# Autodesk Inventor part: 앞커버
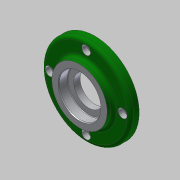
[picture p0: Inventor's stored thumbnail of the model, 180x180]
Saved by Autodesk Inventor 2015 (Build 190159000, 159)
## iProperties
Created: 2019-01
Part Number: 앞커버
Material: 알루미늄 6061
Document SubType Name: Modeling
Designer: mduedu
Density: 1 g/cm^3
Appearance: 알루미늄 - 평지
Author: mduedu
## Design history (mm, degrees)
sketch "스케치1"
  geometry: L1 (0, 0)-(6, 0); L2 (6, 0)-(6, 25); L3 (6, 25)-(0, 25); L4 (0, 25)-(0, 0); L5 (6, 0)-(14, 0); L6 (14, 0)-(14, 40); L7 (14, 40)-(6, 40); L8 (6, 40)-(6, 0); L9 (14, 0)-(19, 0); L10 (19, 0)-(19, 26); L11 (19, 26)-(14, 26); L12 (14, 26)-(14, 0)
  constraints: 24 end point, 6 parallel, 3 horizontal, 3 perpendicular
  dimensions: "d6" = 80 diameter of L7 L5; "d8" = 50 diameter of L3 L1; "d9" = 52 diameter of L11 L9; "d10" = 5 distance of L10.end L11.end; "d11" = 6 distance of L2.end L3.end; "d12" = 19 distance between parallel lines of L4 L10; "d13" = 8 distance of L6.end L7.end (derived)
revolve "회전1" sketch "스케치1" stored, may be unused: angle "d5" = 90 deg
sketch "스케치2"
  geometry: C1 r 13.5 at (0, 0); 1 further point
  constraints: 1 centre point, 1 coincident
  dimensions: "d14" = 27 diameter of C1
extrude "돌출1" cut sketch "스케치2" stored distance "d15" = 10; taper "d16" = 0 deg
sketch "스케치3" dims "d17" = 66
  geometry: 6 further points
  constraints: 2 vertical alignment, 1 coincident, 7 other
  dimensions: "d20" = 360 deg dimension on point (0, 0) point (0, 33) (derived)
sketch "스케치4"
  geometry: 4 further points
  constraints: 4 other
hole "구멍1" sketch "스케치4" at (-33, 0), (0, -33), (33, 0), (0, 33) diameter "d22" = 4.5; stored, may be unused: countersink angle "d26" = 90 deg, drill point angle "d28" = 0 deg; dims "d23" = 6, "d24" = 8, "d25" = 4.6, "d27" = 8
fillet "모깎기1" dims "d29" = 3
sketch "스케치5"
  geometry: C1 r 19 at (0, 0); 1 further point
  constraints: 1 centre point, 1 coincident
  dimensions: "d30" = 38 diameter of C1
extrude "돌출2" cut sketch "스케치5" distance "d31" = 8.3; taper "d32" = 0 deg
fillet "모깎기2" dims "d33" = 3
chamfer "모따기1" distance "d34" = 0.8; stored, may be unused: second distance "d35" = 2, angle "d36" = 30 deg
fillet "모깎기3" dims "d37" = 0.5
sketch "스케치6"
  geometry: C1 r 22 at (0, 0); 1 further point
  constraints: 1 centre point, 1 coincident
  dimensions: "d38" = 44 diameter of C1
extrude "돌출3" cut sketch "스케치6" distance "d39" = 5; taper "d40" = 0 deg
fillet "모깎기4" dims "d41" = 3
chamfer "모따기2" distance "d42" = 1; stored, may be unused: second distance "d43" = 2, angle "d44" = 30 deg
node "솔리드1"
